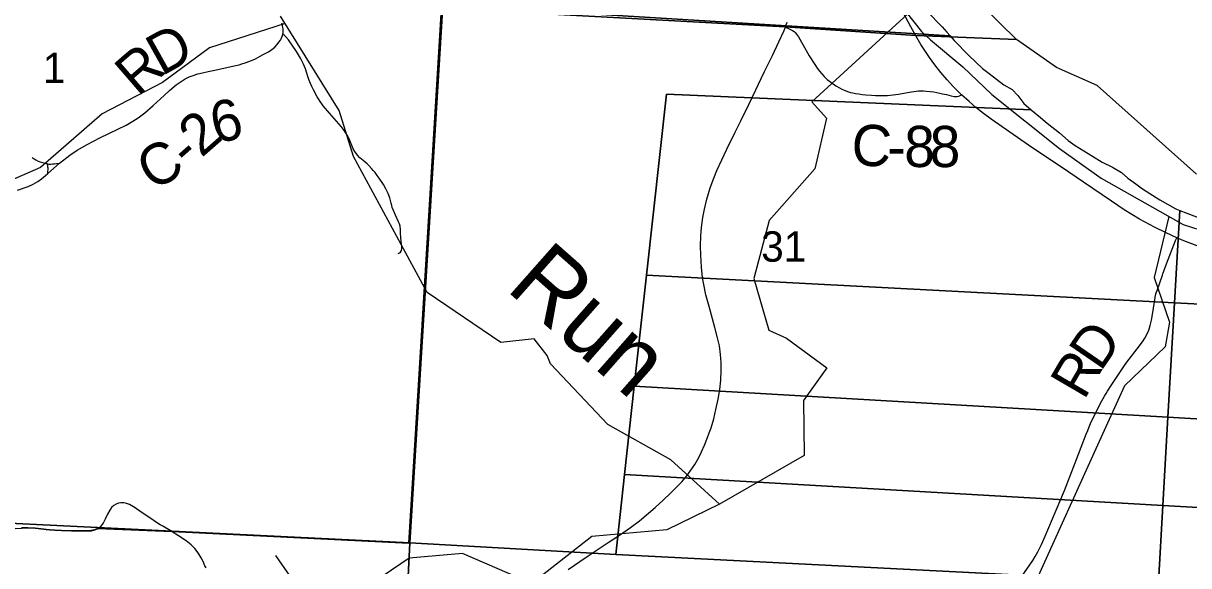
# Model space of a CAD drawing. Extents: x 0 to 34, y 0 to 22.
# Drawn here: x 26.889 to 28.495, y 15.902 to 16.649 of the extents above; entities that cross this region are included whole.
import ezdxf

# ---------------------------------------------------------------- set-up
doc = ezdxf.new("R2010")
doc.units = 0
for name, color, linetype in [('Default', 7, 'Continuous'), ('GM_X_County_Road', 7, 'Continuous'), ('GM_X_County_Road_Text', 7, 'Continuous'), ('GM_X_Major_River', 7, 'Continuous'), ('GM_X_Minor_River', 7, 'Continuous'), ('GM_X_Minor_River_Text', 7, 'Continuous'), ('GM_X_Section', 7, 'Continuous'), ('GM_X_Section_Text', 7, 'Continuous'), ('GM_X_State_Route', 7, 'Continuous'), ('GM_X_Township_Road', 7, 'Continuous'), ('SH_Text', 7, 'Continuous')]:
    doc.layers.add(name, color=color, linetype=linetype)

msp = doc.modelspace()

# ---------------------------------------------------------------- linework, layer by layer
at = {"layer": 'Default'}
for points in [[(27.5436, 17.9511), (27.477, 16.8624), (27.4654, 16.67), (27.9391, 16.6444), (28.1188, 16.6326), (28.2577, 16.6271), (28.2114, 16.6724), (28.1579, 16.7413), (28.0739, 16.8728), (28.0259, 16.9726), (27.9832, 17.1768), (27.9665, 17.3472), (27.9669, 17.3673), (27.9525, 17.8831), (27.9847, 17.9912)], [(26.8866, 15.9536), (26.8953, 15.9537), (26.9051, 15.9532), (26.9173, 15.9519), (26.9205, 15.9516), (26.9254, 15.951), (26.9323, 15.9503), (26.9416, 15.9499), (26.9554, 15.9494), (26.9643, 15.9495), (26.9763, 15.9496), (26.9823, 15.9498), (26.987, 15.951), (26.9903, 15.9525), (26.9911, 15.953), (27.0939, 15.9486), (27.4201, 15.9327), (27.4654, 16.67), (27.477, 16.8624), (27.5436, 17.9511)], [(28.5059, 16.4411), (28.3687, 16.5634), (28.313, 16.5881), (28.2577, 16.6271), (28.1188, 16.6326), (27.9391, 16.6444), (27.4654, 16.67), (27.4201, 15.9327), (27.0939, 15.9486), (26.9911, 15.953), (26.9903, 15.9525), (26.987, 15.951), (26.9823, 15.9498), (26.9763, 15.9496), (26.9643, 15.9495), (26.9554, 15.9494), (26.9416, 15.9499), (26.9323, 15.9503), (26.9254, 15.951), (26.9205, 15.9516), (26.9173, 15.9519), (26.9051, 15.9532), (26.8953, 15.9537), (26.8866, 15.9536)]]:
    msp.add_lwpolyline(points, dxfattribs=at)
at = {"layer": 'GM_X_County_Road'}
for points in [[(26.9226, 16.4421), (26.939, 16.4566), (26.953, 16.4676), (26.9633, 16.4745), (26.9768, 16.4821), (26.9944, 16.4913), (27.019, 16.5032), (27.0308, 16.509), (27.04, 16.5142), (27.0473, 16.519), (27.0562, 16.5258), (27.0681, 16.5359), (27.0831, 16.5499), (27.0904, 16.5566), (27.0994, 16.5642), (27.1063, 16.5692), (27.1121, 16.5728), (27.1174, 16.5754), (27.1231, 16.5775), (27.1296, 16.5796), (27.136, 16.5811), (27.1437, 16.5827), (27.1529, 16.5846), (27.1756, 16.5897), (27.1816, 16.5911), (27.1864, 16.5922), (27.19, 16.5933), (27.1946, 16.5949), (27.2012, 16.5972), (27.2087, 16.6003), (27.2184, 16.6056), (27.2268, 16.6101), (27.2315, 16.6132), (27.2354, 16.6163), (27.2389, 16.6199), (27.2411, 16.623), (27.2432, 16.626), (27.2441, 16.6276), (27.2452, 16.6301), (27.2459, 16.6322), (27.2465, 16.6344), (27.247, 16.6365), (27.2472, 16.6391), (27.2469, 16.6415), (27.2465, 16.6434), (27.2459, 16.6462), (27.245, 16.6496)], [(27.9393, 16.6439), (27.9442, 16.6417), (27.947, 16.6404), (27.949, 16.6393), (27.9511, 16.638), (27.9529, 16.6365), (27.9546, 16.6344), (27.9559, 16.6326), (27.9571, 16.6306), (27.9631, 16.6202), (27.9721, 16.6045), (27.9799, 16.5923), (27.9831, 16.5876), (27.9862, 16.5832), (27.9893, 16.5794), (27.9927, 16.5757), (27.9968, 16.5719), (28.0017, 16.5681), (28.0089, 16.5631), (28.0139, 16.5601), (28.0171, 16.5585), (28.0195, 16.5574), (28.0226, 16.5562), (28.026, 16.5549), (28.0291, 16.554), (28.0323, 16.5533), (28.0357, 16.5526), (28.0403, 16.5519), (28.045, 16.5513), (28.05, 16.5507), (28.0579, 16.5501), (28.0635, 16.5497), (28.0682, 16.5496), (28.0719, 16.5495), (28.076, 16.5496), (28.0799, 16.5498), (28.0837, 16.5501), (28.0878, 16.5506), (28.0916, 16.5511), (28.0951, 16.5517), (28.1075, 16.5538), (28.1131, 16.5548), (28.1164, 16.5554), (28.1194, 16.5558), (28.1225, 16.556), (28.1257, 16.5561), (28.1294, 16.5561), (28.1337, 16.5558), (28.1386, 16.5553), (28.1437, 16.5546), (28.1481, 16.5538), (28.1523, 16.553), (28.1558, 16.5522), (28.1613, 16.5509), (28.1678, 16.5494), (28.1719, 16.5485), (28.1739, 16.5483), (28.176, 16.5484), (28.1781, 16.549), (28.1819, 16.5505)], [(26.8811, 16.419), (26.8954, 16.4243), (26.9026, 16.4274), (26.9089, 16.4312), (26.9139, 16.4347), (26.9196, 16.4394), (26.9226, 16.4421)], [(28.4595, 16.304), (28.4645, 16.3176), (28.4771, 16.35), (28.4785, 16.3537)], [(28.2648, 15.8862), (28.2802, 15.9088), (28.2835, 15.9141), (28.2871, 15.9205), (28.29, 15.926), (28.2921, 15.9305), (28.2973, 15.9424), (28.3123, 15.9779), (28.3239, 16.0051), (28.3361, 16.0372), (28.3537, 16.0828), (28.3559, 16.0881), (28.358, 16.093), (28.3599, 16.0975), (28.3698, 16.1184), (28.3754, 16.1289), (28.3791, 16.1353), (28.3813, 16.1391), (28.3832, 16.1422), (28.3889, 16.1511), (28.4057, 16.1761), (28.4099, 16.1821), (28.4273, 16.2046), (28.4323, 16.2117), (28.4345, 16.2153), (28.4372, 16.2202), (28.4399, 16.2264), (28.4421, 16.2328), (28.4439, 16.24), (28.4452, 16.2479), (28.4478, 16.2651), (28.4488, 16.271), (28.4495, 16.2744), (28.4504, 16.2777), (28.4514, 16.2809), (28.4588, 16.302), (28.4595, 16.304)], [(27.0935, 15.9485), (27.0913, 15.9498), (27.0811, 15.9558), (27.0777, 15.9579), (27.0754, 15.9594), (27.0718, 15.9614), (27.0696, 15.963), (27.0672, 15.9647), (27.0595, 15.9697), (27.0497, 15.9768), (27.0449, 15.9801), (27.0433, 15.9811), (27.0407, 15.9828), (27.0352, 15.9857), (27.031, 15.9873), (27.0273, 15.9881), (27.0235, 15.9881), (27.0203, 15.9876), (27.0168, 15.9864), (27.0138, 15.9847), (27.0106, 15.9817), (27.0082, 15.9782), (27.0051, 15.9725), (27.0016, 15.9655), (26.9989, 15.9601), (26.9955, 15.9556), (26.9928, 15.9534), (26.9913, 15.9525), (26.9905, 15.952)], [(26.9905, 15.952), (26.9872, 15.9505), (26.9825, 15.9493), (26.9765, 15.9491), (26.9645, 15.949), (26.9556, 15.9489), (26.9418, 15.9494), (26.9325, 15.9498), (26.9257, 15.9504), (26.9207, 15.9511), (26.9175, 15.9514), (26.9053, 15.9527), (26.8956, 15.9532), (26.8868, 15.953), (26.8775, 15.9525), (26.8763, 15.9523)], [(27.1408, 15.8984), (27.1393, 15.9015), (27.137, 15.9072), (27.134, 15.9124), (27.1311, 15.917), (27.1284, 15.9209), (27.1251, 15.925), (27.1202, 15.9302), (27.1134, 15.9357), (27.103, 15.9426), (27.0942, 15.9481), (27.0935, 15.9485)]]:
    msp.add_lwpolyline(points, dxfattribs=at)
at = {"layer": 'GM_X_Major_River'}
msp.add_lwpolyline([(28.0866, 16.6892), (28.1269, 16.6378), (28.1394, 16.6264), (28.1838, 16.5894), (28.2237, 16.5512), (28.3169, 16.4768), (28.3742, 16.4357), (28.4875, 16.372), (28.5106, 16.3645)], dxfattribs=at)
at = {"layer": 'GM_X_Minor_River'}
for points in [[(28.1078, 16.6622), (27.9757, 16.5411), (27.9961, 16.5185), (27.9796, 16.4485), (27.9167, 16.3773), (27.8958, 16.2974), (27.9164, 16.2263), (27.9409, 16.2151), (27.9965, 16.1742), (27.964, 16.1291), (27.965, 16.0532), (27.8486, 15.9861), (27.7814, 16.0474), (27.6945, 16.096), (27.6156, 16.1799), (27.6109, 16.1913), (27.5932, 16.2143), (27.5469, 16.2093), (27.4454, 16.2782), (27.3442, 16.4656), (27.3244, 16.5292), (27.2434, 16.659)], [(27.2498, 16.6488), (27.1456, 16.6153), (27.0809, 16.5676), (26.9976, 16.5244), (26.9124, 16.4504), (26.732, 16.3717), (26.6058, 16.3569), (26.5466, 16.378), (26.5261, 16.4116), (26.4522, 16.4277), (26.378, 16.3871), (26.2742, 16.3065), (26.2023, 16.293), (26.1133, 16.3901), (26.0364, 16.4107), (26.0249, 16.42), (25.953, 16.4558)], [(28.4678, 16.383), (28.4473, 16.2989), (28.4687, 16.2373), (28.4626, 16.2034), (28.4068, 16.1494), (28.3695, 16.0675), (28.2854, 15.8822), (28.2465, 15.7479), (28.2089, 15.6967), (28.1244, 15.6246), (28.0888, 15.5286), (27.98, 15.372), (27.9658, 15.356)], [(27.8486, 15.9861), (27.7758, 15.951), (27.6723, 15.9417), (27.5896, 15.8768), (27.4942, 15.9181), (27.4206, 15.9121), (27.3119, 15.8379), (27.2763, 15.8588), (27.2368, 15.9154)]]:
    msp.add_lwpolyline(points, dxfattribs=at)
at = {"layer": 'GM_X_Section'}
for points in [[(27.484, 16.9363), (27.4673, 16.6748), (27.4216, 15.9328), (26.3734, 15.9843), (26.3613, 15.9846), (26.4248, 16.9831)], [(28.0084, 16.9087), (28.0104, 16.901), (28.0177, 16.8817), (28.0246, 16.8646), (28.0303, 16.8521), (28.0341, 16.8438), (28.0467, 16.8189), (28.0544, 16.8015), (28.0597, 16.792), (28.0658, 16.7784), (28.0719, 16.7655), (28.0753, 16.7591), (28.0822, 16.7406), (28.0864, 16.733), (28.0967, 16.7156), (28.1055, 16.7009), (28.1131, 16.6888), (28.1215, 16.6782), (28.1344, 16.6653), (28.1553, 16.6442), (28.1618, 16.637), (28.1661, 16.6321), (27.4673, 16.6748), (27.484, 16.9363)], [(28.1661, 16.6321), (28.1717, 16.6257), (28.1922, 16.6049), (28.2108, 16.5868), (28.2199, 16.58), (28.2302, 16.5721), (28.2405, 16.5645), (28.2518, 16.5578), (28.2598, 16.5498), (28.2678, 16.5389), (28.278, 16.5301), (27.7753, 16.5515), (27.7478, 16.3019), (27.731, 16.1489), (27.7176, 16.0274), (27.7054, 15.9168), (27.4216, 15.9328), (27.4673, 16.6748)], [(28.278, 16.5301), (28.291, 16.5196), (28.3001, 16.5117), (28.3172, 16.4981), (28.329, 16.4876), (28.3385, 16.4808), (28.3624, 16.4661), (28.3757, 16.4578), (28.3901, 16.451), (28.4023, 16.4435), (28.411, 16.4359), (28.4224, 16.428), (28.4315, 16.4209), (28.4551, 16.4058), (28.4763, 16.3937), (28.4783, 16.3929), (28.4829, 16.3911), (28.4755, 16.264), (27.7478, 16.3019), (27.7753, 16.5515)], [(28.4755, 16.264), (28.4829, 16.3911), (28.4923, 16.3873), (28.5154, 16.3787), (28.5302, 16.3735), (28.5507, 16.3697), (28.5662, 16.366), (28.5825, 16.3608), (28.6011, 16.351), (28.6213, 16.3401), (28.6482, 16.325), (28.6748, 16.3111), (28.6896, 16.3032), (28.7055, 16.2926), (28.7367, 16.2757), (28.7519, 16.2685), (28.7606, 16.2625), (28.7731, 16.2534), (28.7796, 16.2482)], [(27.7478, 16.3019), (28.4755, 16.264), (28.4664, 16.1061), (27.731, 16.1489)], [(28.4755, 16.264), (28.7796, 16.2482), (28.7914, 16.2387), (28.8122, 16.224), (28.832, 16.2108), (28.8495, 16.1988), (28.8711, 16.1814), (28.8909, 16.1659), (28.9042, 16.155), (28.9175, 16.1429), (28.9361, 16.1244), (28.9479, 16.115), (28.9619, 16.1048), (28.9752, 16.0935), (28.987, 16.0825), (28.9934, 16.0755), (28.4664, 16.1061)], [(28.4664, 16.1061), (28.4594, 15.9845), (27.7176, 16.0274), (27.731, 16.1489)], [(28.9934, 16.0755), (29.0026, 16.0652), (29.0175, 16.0512), (29.0304, 16.0395), (29.0444, 16.0236), (29.0635, 16.0021), (29.073, 15.9919), (29.0829, 15.9794), (29.0901, 15.9704), (29.1, 15.9598), (29.1085, 15.9479), (28.4594, 15.9845), (28.4664, 16.1061)], [(27.7176, 16.0274), (28.4594, 15.9845), (28.4533, 15.8787), (27.7054, 15.9168)], [(26.3734, 15.9843), (27.4216, 15.9328), (27.4099, 15.6936), (27.392, 15.4391), (27.3753, 15.1787), (27.3574, 14.9107), (27.3572, 14.9074), (26.2944, 14.9601)], [(28.4594, 15.9845), (29.1085, 15.9479), (29.1198, 15.9322), (29.1285, 15.9182), (29.151, 15.885), (29.1594, 15.8732), (29.1693, 15.86), (29.1769, 15.8494), (29.1887, 15.8408), (28.6965, 15.8662), (28.4533, 15.8787)], [(27.4216, 15.9328), (27.7054, 15.9168), (28.4533, 15.8787), (28.439, 15.6312), (27.4099, 15.6936)]]:
    msp.add_lwpolyline(points, close=True, dxfattribs=at)
at = {"layer": 'GM_X_State_Route'}
msp.add_line((27.9393, 16.6439), (27.94, 16.6458), dxfattribs=at)
for points in [[(28.119, 16.6321), (28.1119, 16.6445), (28.1046, 16.6581), (28.0963, 16.6741), (28.0682, 16.7288), (28.0445, 16.774), (28.0276, 16.8065), (28.0153, 16.8303), (28.005, 16.8515), (27.9976, 16.868), (27.9914, 16.8829), (27.9863, 16.8963), (27.9809, 16.9122), (27.9757, 16.9289), (27.9742, 16.9341), (27.9689, 16.9528), (27.966, 16.9638)], [(27.8256, 16.2959), (27.8252, 16.2989), (27.8235, 16.3132), (27.8226, 16.3295), (27.8223, 16.3424), (27.8229, 16.3562), (27.8238, 16.3677), (27.8256, 16.3813), (27.8278, 16.3931), (27.8311, 16.4066), (27.8356, 16.4222), (27.8404, 16.4358), (27.8447, 16.4461), (27.8586, 16.4756), (27.8701, 16.4992), (27.8777, 16.5149), (27.8887, 16.5375), (27.8983, 16.5573), (27.9059, 16.5731), (27.9106, 16.5829), (27.9214, 16.6049), (27.9304, 16.6235), (27.9371, 16.6384), (27.9393, 16.6439)], [(27.94, 16.6458), (27.9417, 16.6507)], [(28.4785, 16.3537), (28.4642, 16.3603), (28.4481, 16.3684), (28.4273, 16.3793), (28.4063, 16.3921), (28.3887, 16.404), (28.3501, 16.4302), (28.3297, 16.4441), (28.2743, 16.4814), (28.2226, 16.5169), (28.2121, 16.5248), (28.2018, 16.5331), (28.1924, 16.5413), (28.1819, 16.5505), (28.1709, 16.5616), (28.162, 16.5713), (28.1535, 16.5815), (28.1454, 16.592), (28.138, 16.602), (28.1313, 16.6117), (28.1259, 16.6202), (28.119, 16.6321)], [(28.5314, 16.3337), (28.5275, 16.3349), (28.5163, 16.3388), (28.4994, 16.3451), (28.4885, 16.3494), (28.4785, 16.3537)], [(27.64, 15.8964), (27.6558, 15.9073), (27.6674, 15.915), (27.6948, 15.9334), (27.7107, 15.9437), (27.7256, 15.954), (27.7383, 15.9635), (27.7506, 15.9741), (27.7599, 15.9818), (27.7708, 15.9918), (27.7811, 16.0014), (27.7907, 16.011), (27.7967, 16.0171), (27.8033, 16.0253), (27.8082, 16.0316), (27.8144, 16.0412), (27.8199, 16.0507), (27.8236, 16.0585), (27.8276, 16.0678), (27.8319, 16.0783), (27.8341, 16.0846), (27.8367, 16.0917), (27.8404, 16.104), (27.8435, 16.117), (27.8465, 16.1312), (27.8487, 16.1443), (27.8501, 16.1571), (27.8508, 16.1707), (27.8506, 16.1814), (27.8498, 16.1927), (27.8482, 16.2046), (27.8458, 16.2154), (27.8422, 16.2301), (27.8342, 16.2588), (27.8297, 16.275), (27.8266, 16.2891), (27.8256, 16.2959)]]:
    msp.add_lwpolyline(points, dxfattribs=at)
at = {"layer": 'GM_X_Township_Road'}
for points in [[(27.4056, 16.3318), (27.4074, 16.3327), (27.4088, 16.3338), (27.4101, 16.336), (27.4107, 16.3384), (27.4107, 16.3408), (27.4102, 16.345), (27.4098, 16.3482), (27.4092, 16.3543), (27.4089, 16.3592), (27.4086, 16.3651), (27.4082, 16.3694), (27.4074, 16.3729), (27.406, 16.3757), (27.402, 16.3846), (27.3992, 16.3912), (27.3975, 16.3951), (27.3967, 16.3979), (27.3958, 16.4011), (27.3941, 16.4084), (27.3919, 16.4144), (27.3886, 16.4211), (27.3853, 16.4268), (27.3793, 16.4359), (27.3768, 16.4395), (27.3739, 16.4437), (27.3712, 16.4465), (27.3687, 16.4491), (27.3651, 16.453), (27.3627, 16.4556), (27.3575, 16.46), (27.3529, 16.4639), (27.3494, 16.4676), (27.3459, 16.4724), (27.3436, 16.476), (27.3379, 16.4898), (27.3352, 16.4952), (27.3318, 16.5008), (27.3272, 16.5068), (27.3111, 16.5252), (27.3023, 16.5356), (27.3002, 16.5384), (27.2979, 16.5415), (27.2958, 16.545), (27.294, 16.5479), (27.2887, 16.5576), (27.2867, 16.5619), (27.2847, 16.5661), (27.2826, 16.5717), (27.281, 16.576), (27.2795, 16.5807), (27.2776, 16.5866), (27.275, 16.593), (27.2709, 16.601), (27.2652, 16.6104), (27.2544, 16.6265), (27.2506, 16.6307), (27.2485, 16.6329), (27.2465, 16.6344)], [(26.9009, 16.4644), (26.9037, 16.4623), (26.9062, 16.4608), (26.9092, 16.4592), (26.9122, 16.4582), (26.9159, 16.4572), (26.9193, 16.4563), (26.9215, 16.4558), (26.9242, 16.4552), (26.9268, 16.4551), (26.9291, 16.4553), (26.9319, 16.4556), (26.9348, 16.456), (26.939, 16.4566)], [(26.9226, 16.4421), (26.9229, 16.445), (26.9231, 16.4476), (26.9231, 16.4494), (26.9229, 16.451), (26.9225, 16.4533), (26.9215, 16.4558)]]:
    msp.add_lwpolyline(points, dxfattribs=at)
at = {"layer": 'SH_Text'}
msp.add_lwpolyline([(28.5059, 16.4411), (28.3687, 16.5634), (28.313, 16.5881), (28.2577, 16.6271), (28.2114, 16.6724)], dxfattribs=at)

# ---------------------------------------------------------------- texts
at = {"layer": 'GM_X_County_Road_Text'}
for s, rotation, p in [('D', 29.228, (27.0797, 16.5759)), ('R', 40.8386, (27.0468, 16.5471)), ('6', 13.3433, (27.1543, 16.4828)), ('2', 41.2716, (27.1344, 16.4631)), ('C', 355.9044, (28.0287, 16.4545)), ('8', 359.9506, (28.103, 16.4511)), ('8', 359.9992, (28.1381, 16.451)), ('C', 30.7877, (27.0676, 16.417)), ('-', 41.4489, (27.117, 16.4477)), ('-', 0.0272, (28.0797, 16.451)), ('D', 55.5613, (28.3737, 16.1679)), ('R', 59.6882, (28.3508, 16.1286))]:
    msp.add_text(s, height=0.0568, rotation=rotation, dxfattribs=at).set_placement(p)
at = {"layer": 'GM_X_Minor_River_Text'}
msp.add_text('Run', height=0.0947, rotation=318.511, dxfattribs=at).set_placement((27.5524, 16.2826))
at = {"layer": 'GM_X_Section_Text'}
for s, height, p in [('1', 0.0419, (26.9158, 16.5669)), ('31', 0.04186, (27.9058, 16.3206))]:
    msp.add_text(s, height=height, rotation=0, dxfattribs=at).set_placement(p)

doc.saveas('drawing.dxf')
